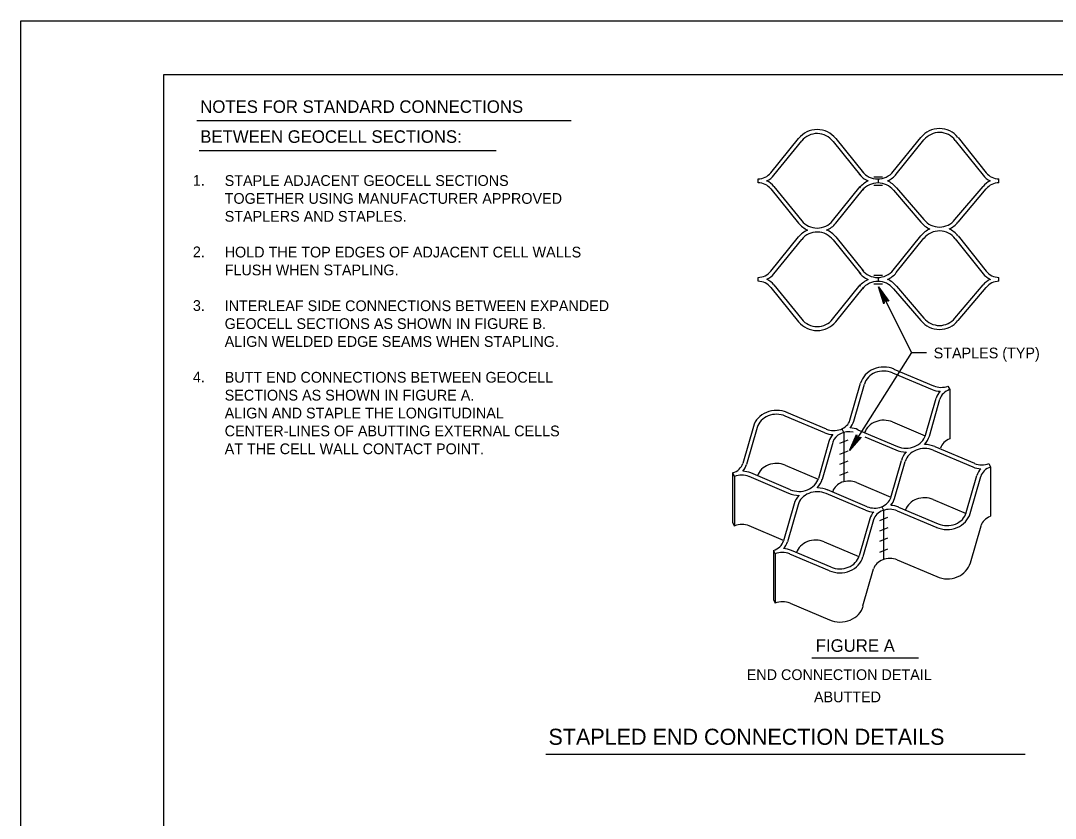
# Model space of a CAD drawing. Extents: x 638850 to 644908, y 297188 to 298900.
# Drawn here: x 638850.4 to 639139.6, y 298424.5 to 298647.5 of the extents above; entities that cross this region are included whole.
import ezdxf

# ---------------------------------------------------------------- set-up
doc = ezdxf.new("R2010")
doc.units = 0
for name, color, linetype in [('1', 7, 'Continuous'), ('2', 7, 'Continuous'), ('3', 7, 'Continuous'), ('PLT-BNDY', 7, 'Continuous')]:
    doc.layers.add(name, color=color, linetype=linetype)

msp = doc.modelspace()

# ---------------------------------------------------------------- linework, layer by layer
at = {"layer": '1'}
for p, q in [((638890.44, 298068.53), (638890.44, 298632.53)), ((638890.44, 298632.53), (639676.44, 298632.53)), ((639090.16, 298573.08), (639099.44, 298554.78)), ((639099.44, 298554.78), (639082.12, 298527.35))]:
    msp.add_line(p, q, dxfattribs=at)
for points in [[(639091.73, 298568.71), (639091.95, 298569.01), (639090.16, 298573.08), (639091.73, 298568.71), (639091.66, 298568.4), (639090.16, 298573.08), (639092.36, 298569.22), (639092.73, 298569.23), (639090.16, 298573.08), (639093.04, 298569.11), (639092.73, 298569.23)], [(639085.07, 298530.94), (639084.7, 298530.98), (639082.12, 298527.35), (639085.07, 298530.94), (639085.37, 298531.04), (639082.12, 298527.35), (639084.3, 298531.22), (639084.11, 298531.54), (639082.12, 298527.35), (639084.06, 298531.87), (639084.11, 298531.54)]]:
    msp.add_lwpolyline(points, dxfattribs=at)
at = {"layer": '2'}
for p, q in [((639056.51, 298602.2), (639056.51, 298603.3)), ((639090.21, 298602.2), (639090.21, 298603.27)), ((639123.85, 298602.2), (639123.85, 298603.3)), ((639068.58, 298586.48), (639068.58, 298586.48)), ((639068.71, 298586.37), (639068.71, 298586.37)), ((639068.71, 298586.37), (639068.71, 298586.37)), ((639068.71, 298586.37), (639068.71, 298586.37)), ((639102.75, 298586.79), (639102.75, 298586.79)), ((639102.89, 298586.68), (639102.89, 298586.68)), ((639102.89, 298586.68), (639102.89, 298586.68)), ((639102.89, 298586.68), (639102.89, 298586.68)), ((639060.84, 298576.9), (639060.84, 298576.9)), ((639060.84, 298576.9), (639060.84, 298576.9)), ((639060.97, 298576.79), (639060.97, 298576.79)), ((639060.97, 298576.79), (639060.97, 298576.79)), ((639060.97, 298576.79), (639060.97, 298576.79)), ((639119.39, 298576.79), (639119.39, 298576.79)), ((639119.39, 298576.79), (639119.39, 298576.79)), ((639119.39, 298576.79), (639119.39, 298576.79)), ((639119.52, 298576.9), (639119.52, 298576.9)), ((639119.52, 298576.9), (639119.52, 298576.9)), ((639056.51, 298574.66), (639056.51, 298575.77)), ((639056.51, 298574.67), (639056.51, 298574.84)), ((639056.51, 298574.84), (639056.51, 298574.84)), ((639056.51, 298574.84), (639056.51, 298574.84)), ((639056.51, 298574.67), (639056.51, 298574.67)), ((639056.51, 298574.67), (639056.51, 298574.67)), ((639056.51, 298574.67), (639056.51, 298574.67)), ((639056.51, 298574.67), (639056.51, 298574.67)), ((639090.14, 298574.64), (639090.14, 298575.57)), ((639123.85, 298574.66), (639123.85, 298575.77)), ((639123.85, 298574.67), (639123.85, 298574.84)), ((639123.85, 298574.84), (639123.85, 298574.84)), ((639123.85, 298574.84), (639123.85, 298574.84)), ((639123.85, 298574.67), (639123.85, 298574.67)), ((639123.85, 298574.67), (639123.85, 298574.67)), ((639123.85, 298574.67), (639123.85, 298574.67)), ((639123.85, 298574.67), (639123.85, 298574.67)), ((639110.09, 298544.37), (639110.09, 298530.61)), ((639080.48, 298532.26), (639080.48, 298518.63)), ((639121.48, 298522.71), (639121.48, 298508.96)), ((639049.4, 298521.07), (639049.4, 298507.23)), ((639049.92, 298520.08), (639049.92, 298506.24)), ((639091.62, 298510.64), (639091.62, 298496.9)), ((639060.79, 298499.41), (639060.79, 298485.66)), ((639061.31, 298498.43), (639061.31, 298484.67))]:
    msp.add_line(p, q, dxfattribs=at)
for centre, radius, start, end in [((639073.04, 298610.41), 6.67, 38.9482, 141.0518), ((639107.21, 298610.71), 6.67, 38.9482, 141.0518), ((639073.04, 298610.41), 5.56, 37.0842, 141.0518), ((639107.21, 298610.71), 5.56, 37.0842, 141.0518), ((639089.96, 298608.83), 5.56, 218.9482, 321.0518), ((639056.51, 298607.93), 4.63, 270, 321.0518), ((639056.51, 298597.57), 5.73, 38.9482, 65.0889), ((639056.51, 298607.93), 5.73, 295.0809, 321.0518), ((639089.96, 298608.83), 6.67, 218.9482, 246.0034), ((639090.03, 298596.61), 6.67, 113.972, 141.0518), ((639090.03, 298596.61), 6.67, 38.9482, 66.4416), ((639089.96, 298608.83), 6.67, 294.957, 321.0518), ((639123.85, 298607.93), 5.73, 218.9482, 244.8629), ((639123.85, 298597.57), 5.73, 114.998, 141.0518), ((639123.85, 298607.93), 4.63, 218.9482, 270), ((639056.51, 298597.57), 4.63, 38.9482, 90), ((639090.03, 298596.61), 5.56, 38.9482, 141.0518), ((639123.85, 298597.57), 4.63, 90, 141.0518), ((639073.04, 298595.1), 6.67, 218.9482, 246.2169), ((639073.04, 298595.1), 5.56, 218.9482, 321.0518), ((639073.04, 298595.1), 6.67, 293.0025, 321.0518), ((639107.21, 298595.4), 6.67, 218.9482, 246.4776), ((639107.21, 298595.4), 5.56, 218.9482, 321.0518), ((639107.21, 298595.4), 6.67, 293.7113, 321.0518), ((639073.04, 298582.87), 6.67, 113.8771, 141.0518), ((639073.04, 298582.87), 5.56, 37.0842, 141.0518), ((639073.04, 298582.87), 6.67, 38.9482, 66.8153), ((639107.21, 298583.18), 6.67, 113.4918, 141.0518), ((639107.21, 298583.18), 5.56, 37.0842, 141.0518), ((639107.21, 298583.18), 6.67, 38.9482, 66.2297), ((639056.51, 298580.4), 4.63, 270, 321.0518), ((639056.51, 298580.4), 5.73, 295.928, 321.0518), ((639089.96, 298581.29), 6.67, 218.9482, 246.5905), ((639089.96, 298581.29), 5.56, 218.9482, 321.0518), ((639089.96, 298581.29), 6.67, 294.0718, 321.0518), ((639123.85, 298580.4), 5.73, 218.9482, 245.1993), ((639123.85, 298580.4), 4.63, 218.9482, 270), ((639056.51, 298570.04), 4.63, 38.9482, 90), ((639056.51, 298570.04), 5.73, 38.9482, 64.564), ((639090.03, 298569.08), 6.67, 113.9178, 141.0518), ((639090.03, 298569.08), 5.56, 38.9482, 141.0518), ((639090.03, 298569.08), 6.67, 38.9482, 66.7705), ((639123.85, 298570.04), 5.73, 115.0093, 141.0518), ((639123.85, 298570.04), 4.63, 90, 141.0518), ((639073.04, 298567.56), 6.67, 218.9482, 321.0518), ((639073.04, 298567.56), 5.56, 218.9482, 321.0518), ((639107.21, 298567.87), 6.67, 218.9482, 321.0518), ((639107.21, 298567.87), 5.56, 218.9482, 321.0518)]:
    msp.add_arc(centre, radius, start, end, dxfattribs=at)
for centre, major_axis, ratio, start_param, end_param in [((639091.64, 298544.76), (6.67, 0), 0.888265, 1.118214, 2.89815), ((639091.64, 298544.76), (5.56, 0), 0.866025, 1.118214, 2.89815), ((639107.66, 298548.87), (4.63, 0), 0.83397, 4.2577, 5.136467), ((639107.66, 298548.87), (5.73, 0), 0.866025, 4.2577, 4.666761), ((639111.85, 298540.81), (-5.73, 0), 0.866025, 5.602086, 6.039743), ((639111.85, 298540.81), (-4.63, 0), 0.83397, 5.107067, 6.039743), ((639061.69, 298532.67), (6.67, 0), 0.884793, 1.114266, 2.89815), ((639061.69, 298532.67), (5.56, 0), 0.866025, 1.116107, 2.898198), ((639077.65, 298536.77), (4.69, 0), 0.822599, 4.2577, 6.033069), ((639091.64, 298531.01), (5.56, 0), 0.866025, 1.118214, 2.853084), ((639081.96, 298528.72), (-4.69, 0), 0.822599, 4.465307, 6.033069), ((639077.71, 298536.77), (5.73, 0), 0.866025, 5.606325, 6.039743), ((639081.9, 298528.72), (-5.73, 0), 0.866025, 4.2577, 4.65227), ((639077.71, 298536.77), (5.73, 0), 0.866025, 4.2577, 4.654434), ((639081.9, 298528.72), (-5.73, 0), 0.866025, 5.611299, 6.039743), ((639097.92, 298532.82), (-5.56, 0), 0.866025, 1.116107, 2.898198), ((639097.92, 298532.82), (-6.67, 0), 0.884793, 2.446418, 2.89815), ((639111.99, 298527.1), (-4.63, 0), 0.83397, 5.136145, 6.039743), ((639097.92, 298532.82), (-6.67, 0), 0.884793, 1.114266, 1.576823), ((639103.04, 298523.11), (5.56, 0), 0.866025, 1.118214, 2.89815), ((639103.04, 298523.11), (6.67, 0), 0.888265, 1.118214, 1.566568), ((639103.04, 298523.11), (6.67, 0), 0.888265, 2.43865, 2.89815), ((639047.76, 298524.68), (4.63, 0), 0.83397, 5.074591, 6.039743), ((639047.76, 298524.68), (5.73, 0), 0.866025, 5.609674, 6.039743), ((639051.95, 298516.62), (-5.73, 0), 0.866025, 4.2577, 4.661976), ((639061.69, 298518.91), (5.56, 0), 0.866025, 1.116107, 2.853084), ((639119.06, 298527.21), (5.73, 0), 0.866025, 4.2577, 4.660327), ((639119.06, 298527.21), (4.63, 0), 0.83397, 4.2577, 5.155781), ((639123.25, 298519.16), (-5.73, 0), 0.866025, 5.606387, 6.039743), ((639123.25, 298519.16), (-4.63, 0), 0.83397, 5.105249, 6.039743), ((639051.95, 298516.62), (-4.63, 0), 0.83397, 4.2577, 5.164533), ((639067.97, 298520.73), (-5.56, 0), 0.866025, 1.118214, 2.89815), ((639067.97, 298520.73), (-6.67, 0), 0.888265, 2.44347, 2.89815), ((639081.94, 298514.96), (-4.69, 0), 0.822599, 4.2577, 6.033069), ((639073.08, 298511.01), (5.56, 0), 0.866025, 1.116107, 2.898198), ((639073.08, 298511.01), (6.67, 0), 0.884793, 1.114266, 1.565765), ((639067.97, 298520.73), (-6.67, 0), 0.888265, 1.118214, 1.580801), ((639073.08, 298511.01), (6.67, 0), 0.884793, 2.433668, 2.89815), ((639089.04, 298515.12), (4.69, 0), 0.822599, 4.2577, 6.033069), ((639089.11, 298515.12), (5.73, 0), 0.866025, 5.621644, 6.039743), ((639103.04, 298509.35), (5.56, 0), 0.866025, 1.118214, 2.839922), ((639089.11, 298515.12), (5.73, 0), 0.866025, 4.2577, 4.666348), ((639093.3, 298507.06), (-5.73, 0), 0.866025, 5.58623, 6.039743), ((639093.36, 298507.06), (-4.69, 0), 0.822599, 4.2577, 6.033069), ((639093.3, 298507.06), (-5.73, 0), 0.866025, 4.2577, 4.650421), ((639109.32, 298511.17), (-6.67, 0), 0.884793, 1.114266, 2.89815), ((639109.32, 298511.17), (-5.56, 0), 0.866025, 1.116107, 2.898198), ((639123.32, 298505.38), (-4.63, 0), 0.83397, 5.136145, 6.039743), ((639052, 298502.8), (-4.63, 0), 0.83397, 4.2577, 5.155781), ((639059.15, 298503.02), (4.63, 0), 0.83397, 5.075977, 6.039743), ((639059.15, 298503.02), (5.73, 0), 0.866025, 5.612704, 6.039743), ((639072.57, 298497.47), (5.56, 0), 0.866025, 1.118214, 2.853086), ((639063.34, 298494.97), (-4.63, 0), 0.83397, 4.2577, 5.168793), ((639063.34, 298494.97), (-5.73, 0), 0.866025, 4.2577, 4.658076), ((639079.37, 298499.07), (-6.67, 0), 0.888265, 1.118214, 2.89815), ((639079.37, 298499.07), (-5.56, 0), 0.866025, 1.118214, 2.89815), ((639093.33, 298493.31), (-4.69, 0), 0.822599, 4.2577, 6.033069), ((639109.39, 298497.38), (-6.67, 0), 0.884793, 1.114266, 2.89815), ((639063.4, 298481.22), (-4.69, 0), 0.822599, 4.2577, 5.173547), ((639079.46, 298485.3), (-6.67, 0), 0.884793, 1.114266, 2.89815)]:
    msp.add_ellipse(centre, major_axis=major_axis, ratio=ratio, start_param=start_param, end_param=end_param, dxfattribs=at)
at = {"layer": '3'}
for p, q in [((638899.71, 298619.59), (639004.25, 298619.59)), ((639060.11, 298605.02), (639067.85, 298614.6)), ((639060.97, 298604.33), (639068.71, 298613.9)), ((639078.22, 298614.6), (639085.96, 298605.02)), ((639094.29, 298605.33), (639102.03, 298614.91)), ((639095.15, 298604.63), (639102.89, 298614.21)), ((639111.65, 298614.07), (639119.39, 298604.33)), ((639112.4, 298614.91), (639120.25, 298605.02)), ((638900.31, 298611.21), (638983.32, 298611.21)), ((639077.47, 298613.76), (639085.21, 298604.18)), ((639088.84, 298603.89), (639091.31, 298603.88)), ((639060.11, 298600.48), (639067.85, 298590.9)), ((639060.97, 298601.17), (639068.71, 298591.6)), ((639077.36, 298591.6), (639085.1, 298601.17)), ((639078.22, 298590.9), (639085.96, 298600.48)), ((639088.84, 298601.51), (639091.31, 298601.52)), ((639094.35, 298600.11), (639102.03, 298591.21)), ((639095.21, 298600.8), (639102.89, 298591.91)), ((639111.54, 298591.91), (639119.39, 298601.17)), ((639112.4, 298591.21), (639120.25, 298600.48)), ((639060.11, 298577.49), (639067.85, 298587.06)), ((639060.97, 298576.79), (639068.71, 298586.37)), ((639077.47, 298586.23), (639085.21, 298576.65)), ((639078.22, 298587.06), (639085.96, 298577.49)), ((639094.29, 298577.8), (639102.03, 298587.37)), ((639095.15, 298577.1), (639102.89, 298586.68)), ((639111.65, 298586.53), (639119.39, 298576.79)), ((639112.4, 298587.37), (639120.25, 298577.49)), ((639088.84, 298576.35), (639091.31, 298576.35)), ((639060.97, 298573.64), (639068.71, 298564.07)), ((639077.36, 298564.07), (639085.1, 298573.64)), ((639088.84, 298573.98), (639091.31, 298573.98)), ((639111.54, 298564.37), (639119.39, 298573.64)), ((639060.11, 298572.95), (639067.85, 298563.37)), ((639078.22, 298563.37), (639085.96, 298572.95)), ((639094.35, 298572.57), (639102.03, 298563.68)), ((639095.21, 298573.27), (639102.89, 298564.37)), ((639112.4, 298563.68), (639120.25, 298572.95)), ((639099.44, 298554.78), (639103.61, 298554.78)), ((639094.07, 298549.09), (639105.14, 298544.41)), ((639094.51, 298550.11), (639105.58, 298545.43)), ((639082.21, 298535.88), (639085.18, 298546.23)), ((639083.28, 298535.58), (639086.24, 298545.92)), ((639109.57, 298545.35), (639110.09, 298544.37)), ((639103.32, 298531.66), (639106.29, 298542.01)), ((639104.39, 298531.4), (639107.36, 298541.75)), ((639075.19, 298532.31), (639064.13, 298536.99)), ((639075.62, 298533.31), (639064.55, 298537.99)), ((639055.22, 298534.09), (639052.25, 298523.74)), ((639056.29, 298533.83), (639053.32, 298523.48)), ((639079.89, 298533.38), (639080.48, 298532.26)), ((639084.42, 298533.18), (639095.48, 298528.5)), ((639094.07, 298535.34), (639103.26, 298531.45)), ((639079.38, 298529.43), (639081.67, 298530.36)), ((639086.35, 298531.18), (639095.06, 298527.5)), ((639076.34, 298529.91), (639073.37, 298519.57)), ((639077.4, 298529.61), (639074.43, 298519.26)), ((639079.38, 298526.35), (639081.67, 298527.28)), ((639105.47, 298527.44), (639116.54, 298522.75)), ((639105.9, 298528.46), (639116.97, 298523.77)), ((639079.38, 298523.58), (639081.67, 298524.51)), ((639093.61, 298514.22), (639096.57, 298524.57)), ((639094.67, 298513.92), (639097.64, 298524.27)), ((639064.13, 298523.24), (639073.31, 298519.36)), ((639079.38, 298520.5), (639081.67, 298521.43)), ((639121.04, 298523.73), (639121.48, 298522.71)), ((639049.4, 298521.07), (639049.92, 298520.08)), ((639050.18, 298520.18), (639050.18, 298520.18)), ((639065.11, 298515.38), (639054.04, 298520.06)), ((639065.54, 298516.4), (639054.47, 298521.08)), ((639084, 298518.43), (639093.64, 298514.35)), ((639114.71, 298510.01), (639117.68, 298520.35)), ((639115.79, 298509.74), (639118.76, 298520.09)), ((639087.01, 298511.65), (639075.95, 298516.33)), ((639086.59, 298510.65), (639075.53, 298515.34)), ((639105.47, 298513.68), (639114.65, 298509.79)), ((639066.61, 298512.43), (639063.65, 298502.08)), ((639067.69, 298512.17), (639064.72, 298501.82)), ((639091.1, 298511.64), (639091.62, 298510.64)), ((639095.39, 298510.53), (639106.45, 298505.84)), ((639095.81, 298511.52), (639106.87, 298506.84)), ((639049.4, 298507.23), (639049.92, 298506.24)), ((639087.73, 298508.26), (639084.76, 298497.91)), ((639088.79, 298507.95), (639085.83, 298497.61)), ((639090.51, 298507.82), (639092.8, 298508.75)), ((639063.67, 298502.19), (639054.04, 298506.27)), ((639090.58, 298504.88), (639092.87, 298505.81)), ((639115.86, 298495.96), (639118.83, 298506.31)), ((639075, 298501.81), (639084.7, 298497.7)), ((639090.51, 298502.04), (639092.8, 298502.97)), ((639060.79, 298499.41), (639061.31, 298498.43)), ((639061.05, 298499.52), (639061.05, 298499.52)), ((639061.58, 298498.52), (639061.58, 298498.52)), ((639076.5, 298493.72), (639065.43, 298498.41)), ((639076.93, 298494.74), (639065.86, 298499.43)), ((639090.51, 298498.89), (639092.8, 298499.82)), ((639095.39, 298496.77), (639106.45, 298492.09)), ((639085.82, 298483.91), (639088.79, 298494.26)), ((639060.79, 298485.66), (639061.31, 298484.67)), ((639065.46, 298484.68), (639076.52, 298480)), ((639071.59, 298469.43), (639101.32, 298469.43)), ((638997.19, 298442.5), (639131.17, 298442.5))]:
    msp.add_line(p, q, dxfattribs=at)
at = {"layer": 'PLT-BNDY'}
msp.add_lwpolyline([(638850.44, 298647.53), (639691.44, 298647.53), (639691.44, 298053.53), (638850.44, 298053.53)], close=True, dxfattribs=at)

# ---------------------------------------------------------------- texts
at = {"layer": '1'}
msp.add_text('STAPLES (TYP)', height=3, dxfattribs=at).set_placement((639105.6, 298553.12))
at = {"layer": '3'}
for s, height, p in [('NOTES FOR STANDARD CONNECTIONS', 3.5, (638900.62, 298621.76)), ('BETWEEN GEOCELL SECTIONS:', 3.5, (638900.62, 298613.38)), ('1.', 3, (638898.56, 298601.39)), ('STAPLE ADJACENT GEOCELL SECTIONS', 3, (638907.45, 298601.33)), ('TOGETHER USING MANUFACTURER APPROVED', 3, (638907.45, 298596.33)), ('STAPLERS AND STAPLES.', 3, (638907.45, 298591.33)), ('2.', 3, (638898.56, 298581.39)), ('HOLD THE TOP EDGES OF ADJACENT CELL WALLS', 3, (638907.45, 298581.33)), ('FLUSH WHEN STAPLING.', 3, (638907.45, 298576.33)), ('3.', 3, (638898.56, 298566.39)), ('INTERLEAF SIDE CONNECTIONS BETWEEN EXPANDED', 3, (638907.45, 298566.33)), ('GEOCELL SECTIONS AS SHOWN IN FIGURE B.', 3, (638907.45, 298561.33)), ('ALIGN WELDED EDGE SEAMS WHEN STAPLING.', 3, (638907.45, 298556.33)), ('4.', 3, (638898.56, 298546.39)), ('BUTT END CONNECTIONS BETWEEN GEOCELL', 3, (638907.45, 298546.33)), ('SECTIONS AS SHOWN IN FIGURE A.', 3, (638907.45, 298541.33)), ('ALIGN AND STAPLE THE LONGITUDINAL', 3, (638907.45, 298536.33)), ('CENTER-LINES OF ABUTTING EXTERNAL CELLS', 3, (638907.45, 298531.33)), ('AT THE CELL WALL CONTACT POINT.', 3, (638907.45, 298526.33)), ('FIGURE A', 3.5, (639072.64, 298471.07)), ('END CONNECTION DETAIL', 3, (639053.35, 298463.18)), ('ABUTTED', 3, (639072.15, 298456.96)), ('STAPLED END CONNECTION DETAILS', 4.5, (638997.94, 298445.07))]:
    msp.add_text(s, height=height, dxfattribs=at).set_placement(p)

doc.saveas('drawing.dxf')
